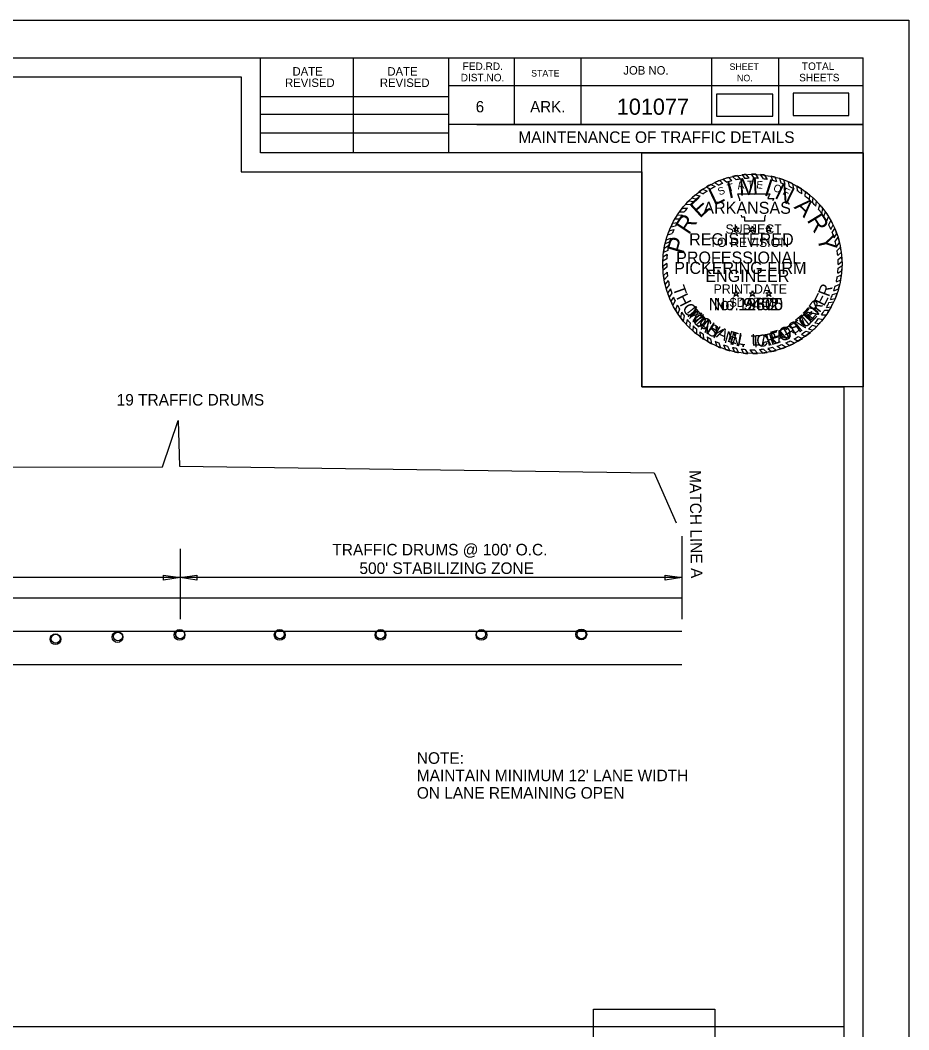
# Model space of a CAD drawing. Extents: x 13528 to 25043, y 7635 to 10612.
# Drawn here: x 16759 to 17221, y 10087 to 10612 of the extents above; entities that cross this region are included whole.
import ezdxf

# ---------------------------------------------------------------- set-up
doc = ezdxf.new("R2010")
doc.units = 0
for name, color, linetype in [('Default', 7, 'Continuous'), ('R_Border Notes', 7, 'Continuous'), ('R_Draft', 7, 'Continuous'), ('R_Revision Date Text', 7, 'Continuous'), ('STAMP_PE_CRAFTON', 7, 'Continuous'), ('STAMP_PE_FOSTER', 7, 'Continuous'), ('STAMP_PE_SEAL-INFO', 7, 'Continuous'), ('STAMP_PE_TAEGTMEYER', 7, 'Continuous'), ('STAMP_PE_TXT', 7, 'Continuous')]:
    doc.layers.add(name, color=color, linetype=linetype)

msp = doc.modelspace()

# ---------------------------------------------------------------- linework, layer by layer
at = {"layer": 'Default'}
for p, q in [((17102.62, 10343.41), (17102.62, 10300.36)), ((16841.84, 10336.93), (16841.84, 10300.36)), ((16841.84, 10321.88), (16389.83, 10321.88)), ((16833.15, 10320.58), (16833.15, 10323.19)), ((16833.15, 10323.19), (16841.84, 10321.88)), ((16841.84, 10321.88), (16833.15, 10320.58)), ((16841.84, 10321.88), (16850.54, 10323.19)), ((17102.62, 10321.88), (16841.84, 10321.88)), ((16850.54, 10320.58), (16841.84, 10321.88)), ((16850.54, 10323.19), (16850.54, 10320.58)), ((17093.93, 10320.58), (17093.93, 10323.19)), ((17093.93, 10323.19), (17102.62, 10321.88)), ((17102.62, 10321.88), (17093.93, 10320.58)), ((16389.83, 10311.48), (17102.62, 10311.48)), ((16389.83, 10294.1), (17102.62, 10294.1)), ((16389.83, 10276.71), (17102.62, 10276.71))]:
    msp.add_line(p, q, dxfattribs=at)
for points in [[(17120.66, 10561.6), (17149.82, 10561.6), (17149.82, 10573.15), (17120.66, 10573.15)], [(17160.43, 10562.08), (17189.43, 10562.08), (17189.43, 10573.57), (17160.43, 10573.57)], [(17119.77, 10047.61), (17056.74, 10047.61), (17056.74, 10097.61), (17119.77, 10097.61)]]:
    msp.add_lwpolyline(points, close=True, dxfattribs=at)
msp.add_lwpolyline([(16394.7, 10352.73), (16414.45, 10378.91), (16832.71, 10379.39), (16840.77, 10403.58), (16841.49, 10379.74), (17088.18, 10376.4), (17099.6, 10350.43)], dxfattribs=at)
for centre, radius in [((16809.31, 10291.02), 2.81), ((16809.54, 10291.3), 2.29), ((16841.56, 10292.13), 2.81), ((16841.79, 10292.45), 2.29), ((16841.91, 10292.44), 2.29), ((16893.61, 10292.13), 2.81), ((16893.68, 10292.43), 2.29), ((16946.03, 10292.13), 2.81), ((16945.95, 10292.43), 2.29), ((16998.45, 10292.13), 2.81), ((16998.22, 10292.43), 2.29), ((17050.32, 10292.39), 2.81), ((17050.49, 10292.43), 2.29), ((16777.06, 10289.91), 2.81), ((16777.18, 10290.15), 2.29)]:
    msp.add_circle(centre, radius, dxfattribs=at)
at = {"layer": 'R_Draft'}
for p, q in [((15615.87, 10592.07), (17196.77, 10592.07)), ((16883.57, 10542.67), (16883.57, 10592.07)), ((16931.97, 10542.67), (16931.97, 10592.07)), ((16981.27, 10592.07), (16981.27, 10542.67)), ((17015.47, 10592.07), (17015.47, 10557.37)), ((17050.17, 10592.07), (17050.17, 10557.37)), ((17118.07, 10592.07), (17118.07, 10557.37)), ((17152.77, 10592.07), (17152.77, 10557.37)), ((17196.77, 9564.77), (17196.77, 10592.07)), ((17196.77, 10577.37), (16981.27, 10577.37)), ((17196.77, 10577.47), (17196.77, 10577.47)), ((16883.57, 10571.97), (16981.27, 10571.97)), ((16883.57, 10562.67), (16981.27, 10562.67)), ((17196.77, 10557.37), (16981.27, 10557.37)), ((16996.07, 10557.37), (17196.77, 10557.37)), ((16883.57, 10552.97), (16981.27, 10552.97)), ((17196.77, 10542.67), (16883.57, 10542.67))]:
    msp.add_line(p, q, dxfattribs=at)
at = {"layer": 'R_Revision Date Text'}
for points in [[(15553.84, 10611.55), (17220.54, 10611.55), (17220.54, 9544.86), (15553.84, 9544.86)], [(17186.77, 10088.42), (15625.87, 10088.42), (15625.87, 10582.07), (16873.57, 10582.07), (16873.57, 10532.67), (16961.27, 10532.67), (17081.77, 10532.67), (17081.77, 10421.01), (17186.77, 10421.01)], [(15625.87, 10582.07), (16873.57, 10582.07), (16873.57, 10532.67), (16961.27, 10532.67), (17081.77, 10532.67), (17081.77, 10421.01), (17186.77, 10421.01), (17186.77, 9574.77), (15625.87, 9574.77)], [(17081.77, 10542.67), (17196.77, 10542.67), (17196.77, 10421.01), (17081.77, 10421.01)]]:
    msp.add_lwpolyline(points, close=True, dxfattribs=at)
at = {"layer": 'STAMP_PE_SEAL-INFO'}
for p, q in [((17124.07, 10528.95), (17125.97, 10527.42)), ((17127.03, 10529.86), (17128.47, 10528.12)), ((17128.97, 10530.35), (17130.74, 10528.63)), ((17131.38, 10530.83), (17132.87, 10528.99)), ((17133.96, 10531.19), (17135.36, 10529.28)), ((17137.63, 10529.42), (17136.07, 10531.39)), ((17140.12, 10529.45), (17138.73, 10531.5)), ((17142.41, 10529.34), (17141.12, 10531.46)), ((17144.94, 10529.09), (17143.48, 10531.31)), ((17147.07, 10528.77), (17145.78, 10531.04)), ((17149.88, 10528.17), (17149.01, 10530.47)), ((17151.89, 10527.63), (17151.09, 10529.98)), ((17154.15, 10526.9), (17153.44, 10529.29)), ((17113.46, 10523.7), (17115.67, 10522.69)), ((17115.4, 10524.92), (17117.56, 10523.81)), ((17117.64, 10526.17), (17119.96, 10525.05)), ((17119.79, 10527.23), (17121.74, 10525.86)), ((17122.33, 10528.31), (17123.81, 10526.68)), ((17156.24, 10526.1), (17155.52, 10528.58)), ((17158.55, 10525.07), (17158.03, 10527.56)), ((17160.77, 10523.92), (17160.34, 10526.47)), ((17162.71, 10522.79), (17162.51, 10525.29)), ((17164.89, 10521.36), (17164.73, 10523.93)), ((17107.76, 10519.23), (17110.05, 10518.54)), ((17109.48, 10520.73), (17112.12, 10520.23)), ((17111.36, 10522.37), (17113.64, 10521.34)), ((17131.64, 10521.34), (17148.36, 10521.34)), ((17132.25, 10519.81), (17131.64, 10521.34)), ((17132.77, 10518.32), (17132.25, 10519.81)), ((17148.36, 10521.34), (17147.23, 10518.88)), ((17147.23, 10518.88), (17150.4, 10518.88)), ((17150.4, 10518.88), (17149.67, 10517.75)), ((17166.69, 10520.02), (17166.86, 10522.46)), ((17168.92, 10518.16), (17169.02, 10520.78)), ((17170.48, 10516.7), (17170.83, 10519.19)), ((17102.74, 10513.84), (17105.49, 10513.95)), ((17104.47, 10515.89), (17107.08, 10515.7)), ((17106.08, 10517.61), (17108.8, 10517.41)), ((17132.8, 10517.75), (17132.77, 10518.32)), ((17172.28, 10514.83), (17172.61, 10517.46)), ((17173.65, 10513.25), (17174.33, 10515.61)), ((17175.27, 10511.17), (17175.94, 10513.66)), ((17098.95, 10508.26), (17101.39, 10508.36)), ((17100.18, 10510.27), (17102.76, 10510.44)), ((17101.35, 10511.99), (17103.87, 10511.96)), ((17133.76, 10509.2), (17133.63, 10510.29)), ((17135.33, 10509.2), (17133.76, 10509.2)), ((17135.33, 10507.05), (17135.33, 10509.2)), ((17145.56, 10508.74), (17145.48, 10507.05)), ((17145.94, 10510.29), (17145.56, 10508.74)), ((17176.37, 10509.59), (17177.26, 10511.91)), ((17177.91, 10507.1), (17178.82, 10509.56)), ((17095.93, 10502.04), (17098.45, 10502.77)), ((17096.85, 10504.2), (17099.36, 10504.72)), ((17097.79, 10506.15), (17100.28, 10506.47)), ((17145.48, 10507.05), (17135.33, 10507.05)), ((17178.91, 10505.27), (17180.04, 10507.49)), ((17180.06, 10502.85), (17181.19, 10505.28)), ((17180.76, 10501.17), (17182.08, 10503.33)), ((17094.4, 10497.49), (17096.78, 10498.34)), ((17095.18, 10500.01), (17097.6, 10500.69)), ((17181.74, 10498.42), (17183.09, 10500.79)), ((17182.27, 10496.6), (17183.74, 10498.86)), ((17095.7, 10494.22), (17093.37, 10492.98)), ((17093.87, 10495.46), (17096.22, 10496.42)), ((17182.94, 10493.8), (17184.53, 10496.04)), ((17183.29, 10491.9), (17185.05, 10493.67)), ((17094.79, 10487.63), (17092.68, 10486.34)), ((17094.97, 10489.75), (17092.79, 10488.35)), ((17095.27, 10491.93), (17093.04, 10490.82)), ((17183.62, 10489.36), (17185.48, 10491.04)), ((17183.78, 10487.27), (17185.73, 10488.73)), ((17094.71, 10485.16), (17092.68, 10483.48)), ((17094.74, 10483.13), (17092.78, 10481.5)), ((17183.79, 10482.65), (17185.88, 10484.04)), ((17183.84, 10484.68), (17185.87, 10486.29)), ((17094.91, 10480.65), (17093.05, 10478.87)), ((17095.17, 10478.5), (17093.4, 10476.64)), ((17182.88, 10475.68), (17185.16, 10476.66)), ((17183.33, 10478.18), (17185.55, 10479.28)), ((17183.59, 10480.12), (17185.76, 10481.4)), ((17095.56, 10476.21), (17093.86, 10474.37)), ((17096.03, 10474.11), (17094.47, 10472.04)), ((17096.65, 10471.88), (17095.17, 10469.79)), ((17181.61, 10470.95), (17184.06, 10471.95)), ((17182.34, 10473.42), (17184.7, 10474.43)), ((17097.35, 10469.76), (17095.94, 10467.7)), ((17098.18, 10467.63), (17096.87, 10465.52)), ((17179.86, 10466.48), (17182.3, 10466.96)), ((17180.93, 10469.05), (17183.35, 10469.7)), ((17099.04, 10465.71), (17097.9, 10463.41)), ((17100.21, 10463.42), (17099.26, 10460.97)), ((17101.39, 10461.4), (17100.47, 10459.05)), ((17176.84, 10460.9), (17179.22, 10460.87)), ((17177.7, 10462.3), (17180.2, 10462.57)), ((17179.06, 10464.8), (17181.5, 10465.14)), ((17102.41, 10459.85), (17101.86, 10457.09)), ((17103.81, 10457.89), (17103.3, 10455.24)), ((17105.33, 10456.01), (17104.9, 10453.41)), ((17173.6, 10456.46), (17175.91, 10456.06)), ((17175.14, 10458.43), (17177.66, 10458.44)), ((17106.84, 10454.32), (17106.53, 10451.71)), ((17108.45, 10452.69), (17108.31, 10450.05)), ((17110.18, 10451.13), (17110.16, 10448.48)), ((17168.38, 10451.14), (17170.74, 10450.49)), ((17170.41, 10453), (17172.61, 10452.31)), ((17171.68, 10454.29), (17174.07, 10453.87)), ((17111.98, 10449.66), (17112.07, 10447.03)), ((17113.67, 10448.41), (17113.85, 10445.82)), ((17115.8, 10447), (17116.11, 10444.44)), ((17117.56, 10445.97), (17118.01, 10443.4)), ((17160.93, 10445.94), (17163.02, 10444.77)), ((17163, 10447.16), (17165.25, 10446.18)), ((17164.72, 10448.3), (17166.92, 10447.35)), ((17167.03, 10450.01), (17169.37, 10449.29)), ((17119.96, 10444.72), (17120.74, 10442.11)), ((17121.82, 10443.88), (17122.69, 10441.32)), ((17124.29, 10442.91), (17125.33, 10440.41)), ((17126.33, 10442.24), (17127.47, 10439.79)), ((17128.87, 10441.55), (17129.94, 10439.22)), ((17130.86, 10441.12), (17132.09, 10438.83)), ((17133.36, 10440.71), (17134.56, 10438.51)), ((17135.55, 10440.47), (17136.92, 10438.33)), ((17137.97, 10440.34), (17139.48, 10438.27)), ((17140.27, 10440.33), (17141.99, 10438.35)), ((17142.86, 10440.46), (17144.49, 10438.56)), ((17145.05, 10440.69), (17146.92, 10438.9)), ((17147.28, 10441.04), (17149.22, 10439.35)), ((17149.74, 10441.56), (17151.63, 10439.94)), ((17152.04, 10442.19), (17154.12, 10440.7)), ((17154.5, 10443), (17156.72, 10441.66)), ((17156.6, 10443.82), (17158.71, 10442.52)), ((17158.89, 10444.87), (17161.31, 10443.81))]:
    msp.add_line(p, q, dxfattribs=at)
msp.add_circle((17139.27, 10484.89), 46.61, dxfattribs=at)
for radius, start, end in [(46.61, 105.2339, 109.0352), (46.61, 99.7525, 102.7765), (44.57, 98.258, 101.0329), (46.61, 93.9381, 96.5517), (44.57, 92.1102, 95.0367), (46.61, 87.7298, 90.6707), (44.57, 85.9628, 88.9097), (46.61, 81.9732, 84.8236), (44.57, 79.9264, 82.696), (46.61, 75.3125, 77.9426), (46.61, 69.6061, 72.3058), (46.61, 123.6199, 126.5906), (46.61, 117.6544, 120.8099), (44.57, 115.6869, 119.1583), (46.61, 111.3124, 114.7026), (44.57, 110.3086, 113.1659), (44.57, 104.0352, 107.3615), (44.57, 73.5575, 76.2314), (44.57, 67.6248, 70.504), (46.61, 63.1329, 66.2704), (44.57, 61.1558, 64.3784), (46.61, 56.9003, 60.0942), (46.61, 129.7326, 132.5376), (44.57, 127.5297, 130.9683), (44.57, 121.9746, 125.11), (44.57, 54.9238, 58.2702), (44.57, 48.3016, 52.0395), (46.61, 50.3492, 53.7159), (46.61, 44.3405, 47.3929), (46.61, 141.6056, 144.4486), (44.57, 139.301, 142.5873), (46.61, 135.4021, 138.3031), (44.57, 133.1331, 136.2562), (44.57, 42.2212, 45.5512), (44.57, 36.135, 39.5311), (46.61, 38.1247, 41.2316), (46.61, 147.0072, 149.899), (44.57, 145.0197, 148.2104), (44.57, 29.9032, 33.6645), (46.61, 31.9614, 35.4294), (46.61, 152.864, 155.5189), (44.57, 156.3402, 159.2319), (44.57, 151.0315, 153.573), (44.57, 23.7732, 27.2211), (46.61, 25.9391, 29.0125), (46.61, 19.9538, 23.3141), (46.61, 164.3068, 166.894), (46.61, 158.4077, 161.0701), (44.57, 162.4331, 165.0013), (44.57, 17.6802, 21.4251), (46.61, 13.8421, 17.4447), (46.61, 170.0003, 172.6878), (44.57, 167.9048, 170.9039), (44.57, 11.5444, 15.2364), (46.61, 7.5852, 10.8621), (46.61, 175.7409, 178.2066), (44.57, 173.73, 176.4734), (44.57, 5.7599, 9.0606), (44.57, 359.7329, 3.0639), (46.61, 1.7215, 4.7268), (46.61, 181.7251, 184.1626), (44.57, 179.6454, 182.2633), (44.57, 353.8632, 357.1274), (46.61, 355.7156, 358.9569), (46.61, 187.4204, 190.1927), (44.57, 185.4539, 188.234), (44.57, 348.0778, 351.3435), (46.61, 349.8305, 353.0885), (46.61, 193.0369, 195.9973), (44.57, 191.2274, 193.9858), (44.57, 196.9675, 199.8353), (44.57, 341.777, 345.0925), (46.61, 343.8925, 347.035), (46.61, 198.8967, 201.6281), (44.57, 202.7761, 205.4791), (44.57, 335.6038, 339.1858), (46.61, 337.3837, 340.9933), (46.61, 204.5479, 207.4328), (46.61, 210.8636, 213.6571), (44.57, 208.7883, 211.7934), (44.57, 323.5851, 327.4407), (46.61, 325.4405, 328.9872), (44.57, 329.5549, 333.2076), (46.61, 331.4037, 334.9332), (46.61, 216.6115, 219.491), (44.57, 214.1838, 217.2747), (44.57, 220.3909, 223.3056), (44.57, 316.6531, 320.3711), (46.61, 318.2846, 321.8043), (46.61, 222.48, 225.3801), (44.57, 226.2494, 229.2407), (44.57, 310.7744, 314.3161), (46.61, 312.4518, 315.6633), (46.61, 228.3665, 231.348), (44.57, 232.229, 234.9336), (46.61, 234.295, 236.9452), (44.57, 238.2223, 240.8353), (44.57, 299.0768, 302.1724), (46.61, 300.621, 303.8703), (44.57, 304.823, 308.5143), (46.61, 306.3721, 310.208), (46.61, 240.1977, 242.8613), (44.57, 244.3204, 246.9486), (46.61, 246.576, 249.1558), (44.57, 250.3491, 253.1216), (46.61, 252.5967, 255.3252), (44.57, 256.505, 259.1192), (44.57, 262.3783, 265.2012), (44.57, 268.3215, 271.277), (44.57, 274.6157, 277.4486), (44.57, 280.3459, 283.5814), (46.61, 282.3199, 285.3702), (44.57, 286.6423, 289.9783), (46.61, 288.5709, 291.9733), (44.57, 292.8745, 296.1185), (46.61, 294.6481, 298.2166), (46.61, 258.4433, 261.1398), (46.61, 264.1978, 267.1009), (46.61, 270.2548, 273.3361), (46.61, 276.4239, 279.4357)]:
    msp.add_arc((17139.27, 10484.89), radius, start, end, dxfattribs=at)
at = {"layer": 'STAMP_PE_TXT'}
for p, q in [((17130.17, 10502.74), (17129.18, 10503.46)), ((17129.18, 10503.46), (17130.41, 10503.46)), ((17129.79, 10501.58), (17130.17, 10502.74)), ((17130.41, 10503.46), (17130.78, 10504.63)), ((17130.78, 10504.63), (17131.16, 10503.46)), ((17131.16, 10503.46), (17132.39, 10503.46)), ((17132.39, 10503.46), (17131.4, 10502.74)), ((17131.4, 10502.74), (17131.78, 10501.58)), ((17138.66, 10502.74), (17137.67, 10503.46)), ((17137.67, 10503.46), (17138.9, 10503.46)), ((17138.28, 10501.58), (17138.66, 10502.74)), ((17138.9, 10503.46), (17139.27, 10504.63)), ((17139.27, 10504.63), (17139.65, 10503.46)), ((17139.65, 10503.46), (17140.88, 10503.46)), ((17140.88, 10503.46), (17139.89, 10502.74)), ((17139.89, 10502.74), (17140.27, 10501.58)), ((17147.15, 10502.74), (17146.16, 10503.46)), ((17146.16, 10503.46), (17147.38, 10503.46)), ((17146.77, 10501.58), (17147.15, 10502.74)), ((17147.38, 10503.46), (17147.76, 10504.63)), ((17147.76, 10504.63), (17148.14, 10503.46)), ((17148.14, 10503.46), (17149.37, 10503.46)), ((17149.37, 10503.46), (17148.38, 10502.74)), ((17148.38, 10502.74), (17148.76, 10501.58)), ((17130.78, 10502.3), (17129.79, 10501.58)), ((17131.78, 10501.58), (17130.78, 10502.3)), ((17139.27, 10502.3), (17138.28, 10501.58)), ((17140.27, 10501.58), (17139.27, 10502.3)), ((17147.76, 10502.3), (17146.77, 10501.58)), ((17148.76, 10501.58), (17147.76, 10502.3)), ((17130.17, 10469.21), (17129.18, 10469.93)), ((17129.18, 10469.93), (17130.41, 10469.93)), ((17129.79, 10468.04), (17130.17, 10469.21)), ((17130.78, 10468.76), (17129.79, 10468.04)), ((17130.41, 10469.93), (17130.78, 10471.09)), ((17130.78, 10471.09), (17131.16, 10469.93)), ((17131.78, 10468.04), (17130.78, 10468.76)), ((17131.16, 10469.93), (17132.39, 10469.93)), ((17132.39, 10469.93), (17131.4, 10469.21)), ((17131.4, 10469.21), (17131.78, 10468.04)), ((17138.66, 10469.21), (17137.67, 10469.93)), ((17137.67, 10469.93), (17138.9, 10469.93)), ((17138.28, 10468.04), (17138.66, 10469.21)), ((17139.27, 10468.76), (17138.28, 10468.04)), ((17138.9, 10469.93), (17139.27, 10471.09)), ((17139.27, 10471.09), (17139.65, 10469.93)), ((17140.27, 10468.04), (17139.27, 10468.76)), ((17139.65, 10469.93), (17140.88, 10469.93)), ((17140.88, 10469.93), (17139.89, 10469.21)), ((17139.89, 10469.21), (17140.27, 10468.04)), ((17147.15, 10469.21), (17146.16, 10469.93)), ((17146.16, 10469.93), (17147.38, 10469.93)), ((17146.77, 10468.04), (17147.15, 10469.21)), ((17147.76, 10468.76), (17146.77, 10468.04)), ((17147.38, 10469.93), (17147.76, 10471.09)), ((17147.76, 10471.09), (17148.14, 10469.93)), ((17148.76, 10468.04), (17147.76, 10468.76)), ((17148.14, 10469.93), (17149.37, 10469.93)), ((17149.37, 10469.93), (17148.38, 10469.21)), ((17148.38, 10469.21), (17148.76, 10468.04))]:
    msp.add_line(p, q, dxfattribs=at)

# ---------------------------------------------------------------- texts
at = {"layer": 'Default'}
for s, p in [('19 TRAFFIC DRUMS', (16808.86, 10411.3)), ("TRAFFIC DRUMS @ 100' O.C.", (16920.98, 10333.44)), ("500' STABILIZING ZONE", (16935.03, 10323.81)), ('NOTE:', (16964.86, 10225.15)), ("MAINTAIN MINIMUM 12' LANE WIDTH", (16964.86, 10216.1)), ('ON LANE REMAINING OPEN', (16964.86, 10207.05))]:
    msp.add_text(s, height=6, dxfattribs=at).set_placement(p)
msp.add_text('MATCH LINE A', height=6, rotation=270.8059, dxfattribs=at).set_placement((17106.54, 10377.7))
at = {"layer": 'R_Border Notes'}
for s, height, p in [('101077', 8.4, (17068.8, 10562.4)), ('MAINTENANCE OF TRAFFIC DETAILS', 6, (17017.62, 10547.77))]:
    msp.add_text(s, height=height, dxfattribs=at).set_placement(p)
at = {"layer": 'R_Draft'}
for s, height, p in [('DATE', 4.396, (16900.26, 10582.75)), ('DATE', 4.396, (16949.56, 10582.75)), ('FED.RD.', 3.91, (16988.67, 10585.67)), ('JOB NO.', 4.396, (17072.17, 10583.27)), ('SHEET', 3.42, (17127.37, 10585.67)), ('TOTAL', 3.91, (17164.97, 10585.67)), ('DIST.NO.', 3.91, (16987.67, 10579.77)), ('STATE', 3.42, (17024.27, 10582.27)), ('NO.', 3.42, (17131.27, 10579.77)), ('SHEETS', 3.91, (17163.57, 10579.77)), ('REVISED', 4.396, (16896.36, 10576.85)), ('REVISED', 4.396, (16945.66, 10576.85)), ('6', 5.86, (16995.47, 10563.67)), ('ARK.', 5.861, (17023.77, 10563.67))]:
    msp.add_text(s, height=height, dxfattribs=at).set_placement(p)
at = {"layer": 'STAMP_PE_CRAFTON'}
msp.add_text('No. 12370', height=6.25, dxfattribs=at).set_placement((17116.58, 10460.87))
for s, rotation, p in [('T', 310.7442, (17104.1, 10459.37)), ('N', 49.2411, (17170.69, 10455)), ('O', 317.6422, (17107.44, 10455.32)), ('N', 324.4537, (17111.67, 10451.39)), ('T', 34.1136, (17162.16, 10448.08)), ('O', 41.8391, (17166.45, 10451.09)), ('Y', 331.1686, (17116.83, 10447.81)), ('A', 20.5125, (17152.68, 10443.66)), ('F', 28.7821, (17157.58, 10445.53)), ('N', 347.4752, (17127.11, 10443.23)), ('C', 6.0117, (17141.63, 10441.59)), ('R', 14.8189, (17147.11, 10442.17)), ('.', 356.8926, (17133.25, 10441.85))]:
    msp.add_text(s, height=6.25, rotation=rotation, dxfattribs=at).set_placement(p)
at = {"layer": 'STAMP_PE_FOSTER'}
msp.add_text('No. 9402', height=6.25, dxfattribs=at).set_placement((17119.2, 10460.87))
for s, rotation, p in [('R', 54.5031, (17172.9, 10458.94)), ('M', 308.339, (17104.85, 10460)), ('E', 46.9613, (17169.28, 10454.84)), ('I', 314.1842, (17108.84, 10455.31)), ('C', 319.8733, (17110.61, 10453.54)), ('T', 39.4194, (17164.99, 10451.09)), ('H', 327.7235, (17115.26, 10449.86)), ('A', 335.7276, (17120.16, 10446.95)), ('F', 15.8691, (17149.45, 10443.66)), ('O', 23.719, (17154.67, 10445.3)), ('S', 31.7234, (17160.23, 10447.95)), ('E', 343.5779, (17125.85, 10444.6)), ('L', 350.8115, (17131.14, 10443.21)), ('L', 1.2666, (17138.84, 10442.43)), ('.', 6.8035, (17144.07, 10442.72))]:
    msp.add_text(s, height=6, rotation=rotation, dxfattribs=at).set_placement(p)
at = {"layer": 'STAMP_PE_SEAL-INFO'}
for s, rotation, p in [('M', 3.1074, (17132.45, 10520.36)), ('I', 342.3164, (17144.79, 10520.7)), ('L', 25.513, (17119.32, 10515.02)), ('I', 12.5248, (17126.96, 10518.82)), ('N', 333.9382, (17150.33, 10519.33)), ('E', 42.3578, (17111.9, 10508.37)), ('A', 315.6579, (17160.5, 10514.2)), ('R', 56.2292, (17106.13, 10499.7)), ('R', 301.3831, (17167.34, 10507.63)), ('P', 73.913, (17103.38, 10489.59)), ('Y', 283.2593, (17172.78, 10498.7))]:
    msp.add_text(s, height=9, rotation=rotation, dxfattribs=at).set_placement(p)
for s, height, p in [('SUBJECT', 4.8, (17125.27, 10500.63)), ('TO REVISION', 4.8, (17116.95, 10493.71)), ('PICKERING FIRM', 6.25, (17098.64, 10479.7)), ('PRINT DATE', 4.8, (17119.06, 10469.46)), ('$DATE$', 4.8, (17127.44, 10462.54))]:
    msp.add_text(s, height=height, dxfattribs=at).set_placement(p)
at = {"layer": 'STAMP_PE_TAEGTMEYER'}
for s, rotation, p in [('T', 289.646, (17097.75, 10472.44)), ('R', 69.57, (17179, 10467.46)), ('H', 296.7339, (17099.55, 10467.51)), ('E', 63.0984, (17176.51, 10462.55)), ('O', 303.7708, (17102.51, 10461.97)), ('M', 314.2033, (17105.78, 10457.22)), ('E', 46.8094, (17169.47, 10453.77)), ('Y', 53.9986, (17173.16, 10457.85)), ('A', 321.0594, (17110.59, 10452.4)), ('M', 39.3, (17164.26, 10449.38)), ('S', 327.8239, (17114.72, 10449.18)), ('G', 23.3052, (17154.27, 10444.2)), ('T', 31.466, (17159.77, 10446.66)), ('N', 344.2727, (17124.21, 10444.14)), ('T', 3.0061, (17138.59, 10441.49)), ('A', 8.9826, (17143.83, 10441.77)), ('E', 17.6836, (17149.02, 10442.54)), ('.', 350.6464, (17130.27, 10442.48))]:
    msp.add_text(s, height=6.25, rotation=rotation, dxfattribs=at).set_placement(p)
msp.add_text('No. 19605', height=6.25, dxfattribs=at).set_placement((17116.58, 10460.87))
at = {"layer": 'STAMP_PE_TXT'}
for s, rotation, p in [('S', 23.5541, (17122.27, 10520.4)), ('T', 16.311, (17126.88, 10522.27)), ('A', 9.0679, (17131.69, 10523.53)), ('T', 1.8248, (17136.63, 10524.18)), ('E', 355.2002, (17141.18, 10524.22)), ('O', 342.2506, (17149.81, 10522.84)), ('F', 335.0075, (17154.64, 10521.15))]:
    msp.add_text(s, height=3.91, rotation=rotation, dxfattribs=at).set_placement(p)
for s, p in [('ARKANSAS', (17113.74, 10510.94)), ('REGISTERED', (17106.36, 10494.59)), ('PROFESSIONAL', (17099.62, 10485.08)), ('ENGINEER', (17114.82, 10475.58))]:
    msp.add_text(s, height=6.25, dxfattribs=at).set_placement(p)

doc.saveas('drawing.dxf')
